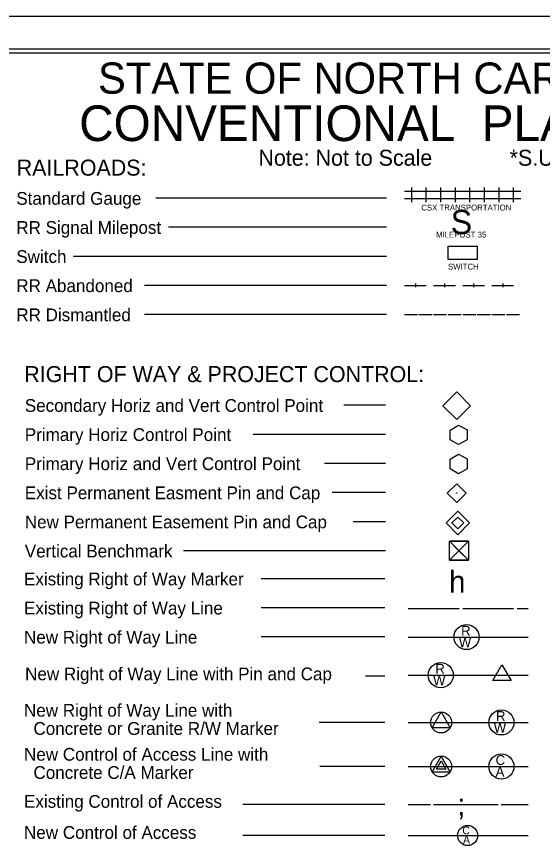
# Model space of a CAD drawing. Extents: x 872928 to 873392, y 373968 to 374173.
# Drawn here: x 872939.7 to 872946.93, y 374081.15 to 374092.55 of the extents above; entities that cross this region are included whole.
import ezdxf

# ---------------------------------------------------------------- set-up
doc = ezdxf.new("R2010")
doc.units = 0
for name, color, linetype in [('Old_Level_1', 7, 'Continuous'), ('Prop ROW Permanent Easement CELL', 7, 'Continuous'), ('Sheet Cutting Line CELL', 7, 'Continuous'), ('Sheet Plot Border Inside CELL', 7, 'Continuous'), ('Sheet Plot Border Outside CELL', 7, 'Continuous'), ('Sheet Symbology CELL', 7, 'Continuous')]:
    doc.layers.add(name, color=color, linetype=linetype)

msp = doc.modelspace()

# ---------------------------------------------------------------- linework, layer by layer
at = {"layer": 'Old_Level_1'}
for p, q in [((872945.749, 374087.2), (872945.749, 374087.2)), ((872945.775, 374086.8), (872945.775, 374086.8)), ((872945.775, 374086.4), (872945.775, 374086.4)), ((872945.749, 374086), (872945.749, 374086)), ((872945.78, 374085.208), (872945.78, 374085.208))]:
    msp.add_line(p, q, dxfattribs=at)
for points in [[(872945.56, 374087.201), (872945.75, 374087.39), (872945.939, 374087.201), (872945.75, 374087.012)], [(872945.658, 374086.468), (872945.775, 374086.533), (872945.893, 374086.469), (872945.891, 374086.334), (872945.774, 374086.266), (872945.658, 374086.332)], [(872945.619, 374086), (872945.749, 374086.129), (872945.879, 374086), (872945.749, 374085.87)], [(872945.65, 374085.338), (872945.909, 374085.338), (872945.909, 374085.078), (872945.65, 374085.078)]]:
    msp.add_lwpolyline(points, close=True, dxfattribs=at)
for points in [[(872945.775, 374086.667), (872945.659, 374086.733), (872945.659, 374086.866), (872945.775, 374086.933), (872945.891, 374086.867), (872945.891, 374086.733), (872945.775, 374086.667)], [(872945.909, 374085.338), (872945.65, 374085.078), (872945.779, 374085.208), (872945.909, 374085.078), (872945.65, 374085.338)], [(872945.779, 374085.208), (872945.909, 374085.338), (872945.65, 374085.338), (872945.779, 374085.208)], [(872945.779, 374085.208), (872945.65, 374085.078), (872945.909, 374085.078), (872945.779, 374085.208)]]:
    msp.add_lwpolyline(points, dxfattribs=at)
msp.add_circle((872945.749, 374086), 0.00253, dxfattribs=at)
at = {"layer": 'Prop ROW Permanent Easement CELL'}
msp.add_line((872945.765, 374085.589), (872945.765, 374085.589), dxfattribs=at)
for points in [[(872945.765, 374085.75), (872945.926, 374085.589), (872945.765, 374085.428), (872945.603, 374085.589)], [(872945.765, 374085.669), (872945.845, 374085.589), (872945.765, 374085.508), (872945.684, 374085.589)]]:
    msp.add_lwpolyline(points, close=True, dxfattribs=at)
at = {"layer": 'Sheet Cutting Line CELL'}
msp.add_line((872962.151, 374092.547), (872928.471, 374092.547), dxfattribs=at)
at = {"layer": 'Sheet Plot Border Inside CELL'}
msp.add_lwpolyline([(872928.731, 374070.996), (872962.061, 374070.996), (872962.061, 374092.098), (872928.731, 374092.098)], close=True, dxfattribs=at)
at = {"layer": 'Sheet Plot Border Outside CELL'}
msp.add_lwpolyline([(872928.471, 374070.547), (872962.151, 374070.547), (872962.151, 374092.547), (872928.471, 374092.547)], close=True, dxfattribs=at)
at = {"layer": 'Sheet Symbology CELL'}
for p, q in [((872945.031, 374090.148), (872945.231, 374090.148)), ((872945.131, 374089.998), (872945.131, 374090.198)), ((872945.231, 374090.148), (872945.431, 374090.148)), ((872945.331, 374089.998), (872945.331, 374090.198)), ((872945.431, 374090.148), (872945.631, 374090.148)), ((872945.531, 374089.998), (872945.531, 374090.198)), ((872945.631, 374090.148), (872945.831, 374090.148)), ((872945.731, 374089.998), (872945.731, 374090.198)), ((872945.831, 374090.148), (872946.031, 374090.148)), ((872945.931, 374089.998), (872945.931, 374090.198)), ((872946.031, 374090.148), (872946.231, 374090.148)), ((872946.131, 374089.998), (872946.131, 374090.198)), ((872946.231, 374090.148), (872946.431, 374090.148)), ((872946.331, 374089.998), (872946.331, 374090.198)), ((872946.431, 374090.148), (872946.631, 374090.148)), ((872946.531, 374089.998), (872946.531, 374090.198)), ((872944.783, 374090.053), (872941.615, 374090.053)), ((872945.031, 374090.048), (872945.231, 374090.048)), ((872945.231, 374090.048), (872945.431, 374090.048)), ((872945.431, 374090.048), (872945.631, 374090.048)), ((872945.631, 374090.048), (872945.831, 374090.048)), ((872945.831, 374090.048), (872946.031, 374090.048)), ((872946.031, 374090.048), (872946.231, 374090.048)), ((872946.231, 374090.048), (872946.431, 374090.048)), ((872946.431, 374090.048), (872946.631, 374090.048)), ((872944.783, 374089.653), (872941.792, 374089.653)), ((872944.783, 374089.253), (872940.485, 374089.253)), ((872945.181, 374088.878), (872945.181, 374088.828)), ((872945.581, 374088.878), (872945.581, 374088.828)), ((872945.981, 374088.878), (872945.981, 374088.828)), ((872946.381, 374088.878), (872946.381, 374088.828)), ((872944.783, 374088.853), (872941.46, 374088.853)), ((872945.031, 374088.853), (872945.331, 374088.853)), ((872945.431, 374088.853), (872945.731, 374088.853)), ((872945.831, 374088.853), (872946.131, 374088.853)), ((872946.231, 374088.853), (872946.531, 374088.853)), ((872944.783, 374088.453), (872941.46, 374088.453)), ((872944.783, 374088.453), (872941.46, 374088.453)), ((872945.031, 374088.453), (872945.211, 374088.453)), ((872945.231, 374088.453), (872945.411, 374088.453)), ((872945.431, 374088.453), (872945.611, 374088.453)), ((872945.631, 374088.453), (872945.811, 374088.453)), ((872945.831, 374088.453), (872946.011, 374088.453)), ((872946.031, 374088.453), (872946.211, 374088.453)), ((872946.231, 374088.453), (872946.411, 374088.453)), ((872946.431, 374088.453), (872946.611, 374088.453)), ((872944.772, 374087.207), (872944.201, 374087.207)), ((872944.772, 374086.807), (872942.952, 374086.807)), ((872944.772, 374086.407), (872943.934, 374086.407)), ((872944.772, 374086.007), (872944.038, 374086.007)), ((872944.772, 374085.607), (872944.325, 374085.607)), ((872944.772, 374085.207), (872941.996, 374085.207)), ((872944.761, 374084.823), (872943.062, 374084.823)), ((872944.761, 374084.423), (872943.062, 374084.423)), ((872945.081, 374084.412), (872945.781, 374084.412)), ((872945.831, 374084.412), (872946.531, 374084.412)), ((872946.581, 374084.412), (872946.731, 374084.412)), ((872944.761, 374084.023), (872943.062, 374084.023)), ((872945.081, 374084.021), (872946.731, 374084.021)), ((872944.761, 374083.486), (872944.496, 374083.486)), ((872945.081, 374083.498), (872946.731, 374083.498)), ((872946.37, 374083.498), (872946.37, 374083.498)), ((872944.761, 374082.846), (872943.861, 374082.846)), ((872945.081, 374082.848), (872946.731, 374082.848)), ((872945.535, 374082.848), (872945.535, 374082.848)), ((872944.761, 374082.241), (872943.868, 374082.241)), ((872945.081, 374082.243), (872946.731, 374082.243)), ((872945.535, 374082.243), (872945.535, 374082.243)), ((872944.761, 374081.722), (872942.81, 374081.722)), ((872945.081, 374081.722), (872945.391, 374081.722)), ((872945.431, 374081.722), (872946.319, 374081.722)), ((872946.359, 374081.722), (872946.731, 374081.722)), ((872944.761, 374081.295), (872942.81, 374081.295)), ((872945.081, 374081.295), (872946.731, 374081.295))]:
    msp.add_line(p, q, dxfattribs=at)
for points in [[(872961.811, 374092.047), (872931.811, 374092.047), (872931.811, 374071.068), (872961.811, 374071.068)], [(872945.631, 374089.392), (872946.031, 374089.392), (872946.031, 374089.21), (872945.631, 374089.21)], [(872946.245, 374083.426), (872946.37, 374083.642), (872946.495, 374083.426)], [(872945.41, 374082.776), (872945.535, 374082.992), (872945.66, 374082.776)], [(872945.41, 374082.171), (872945.66, 374082.171), (872945.535, 374082.387)], [(872945.47, 374082.206), (872945.535, 374082.319), (872945.601, 374082.206)]]:
    msp.add_lwpolyline(points, close=True, dxfattribs=at)
for centre, radius in [((872945.884, 374084.021), 0.172), ((872945.53, 374083.498), 0.172), ((872945.535, 374082.848), 0.144), ((872946.363, 374082.848), 0.172), ((872945.535, 374082.243), 0.144), ((872946.363, 374082.243), 0.172), ((872945.899, 374081.295), 0.138)]:
    msp.add_circle(centre, radius, dxfattribs=at)

# ---------------------------------------------------------------- texts
for s, height, p in [('STATE OF NORTH CAROLINA, DIVISION OF HIGHWAYS', 0.42838, (872940.823, 374091.488)), ('CONVENTIONAL  PLAN SHEET SYMBOLS', 0.48961, (872940.564, 374090.837)), ('RAILROADS:', 0.22, (872939.706, 374090.362)), ('Standard Gauge', 0.175, (872939.7, 374089.962)), ('S', 0.33, (872945.667, 374089.56)), ('RR Signal Milepost', 0.175, (872939.7, 374089.562)), ('Switch', 0.175, (872939.7, 374089.162)), ('RR Abandoned', 0.175, (872939.7, 374088.762)), ('RR Dismantled', 0.175, (872939.7, 374088.362)), ('RIGHT OF WAY & PROJECT CONTROL:', 0.22, (872939.81, 374087.525)), ('Secondary Horiz and Vert Control Point', 0.175, (872939.817, 374087.116)), ('Primary Horiz Control Point', 0.175, (872939.817, 374086.716)), ('Primary Horiz and Vert Control Point', 0.175, (872939.817, 374086.316)), ('Exist Permanent Easment Pin and Cap', 0.175, (872939.817, 374085.916)), ('New Permanent Easement Pin and Cap', 0.175, (872939.817, 374085.516)), ('Vertical Benchmark', 0.175, (872939.817, 374085.116)), ('Existing Right of Way Marker', 0.175, (872939.806, 374084.732)), ('h', 0.3, (872945.645, 374084.632)), ('Existing Right of Way Line', 0.175, (872939.806, 374084.332)), ('New Right of Way Line', 0.175, (872939.806, 374083.932)), ('R', 0.135, (872945.81, 374084.041)), ('W', 0.135, (872945.779, 374083.882)), ('R', 0.135, (872945.456, 374083.519)), ('New Right of Way Line with Pin and Cap', 0.175, (872939.821, 374083.428)), ('W', 0.135, (872945.425, 374083.36)), ('New Right of Way Line with', 0.175, (872939.806, 374082.928)), ('R', 0.135, (872946.289, 374082.869)), ('  Concrete or Granite R/W Marker', 0.175, (872939.806, 374082.678)), ('W', 0.135, (872946.258, 374082.71)), ('New Control of Access Line with', 0.175, (872939.806, 374082.323)), ('C', 0.135, (872946.284, 374082.264)), ('  Concrete C/A Marker', 0.175, (872939.806, 374082.073)), ('A', 0.135, (872946.283, 374082.105)), ('Existing Control of Access', 0.175, (872939.806, 374081.676)), (';', 0.3, (872945.756, 374081.572)), ('New Control of Access', 0.175, (872939.806, 374081.249)), ('C', 0.108, (872945.826, 374081.311)), ('A', 0.108, (872945.836, 374081.181))]:
    msp.add_text(s, height=height, dxfattribs=at).set_placement(p)
for s, height, p in [('Note: Not to Scale', 0.22, (872943.026, 374090.498)), ('*S.U.E. = Subsurface Utility Engineering', 0.22, (872946.476, 374090.498)), ('CSX TRANSPORTATION', 0.08, (872945.263, 374089.883)), ('MILEPOST 35', 0.08, (872945.466, 374089.512)), ('SWITCH', 0.08, (872945.63, 374089.072))]:
    msp.add_text(s, height=height, rotation=360, dxfattribs=at).set_placement(p)

doc.saveas('drawing.dxf')
